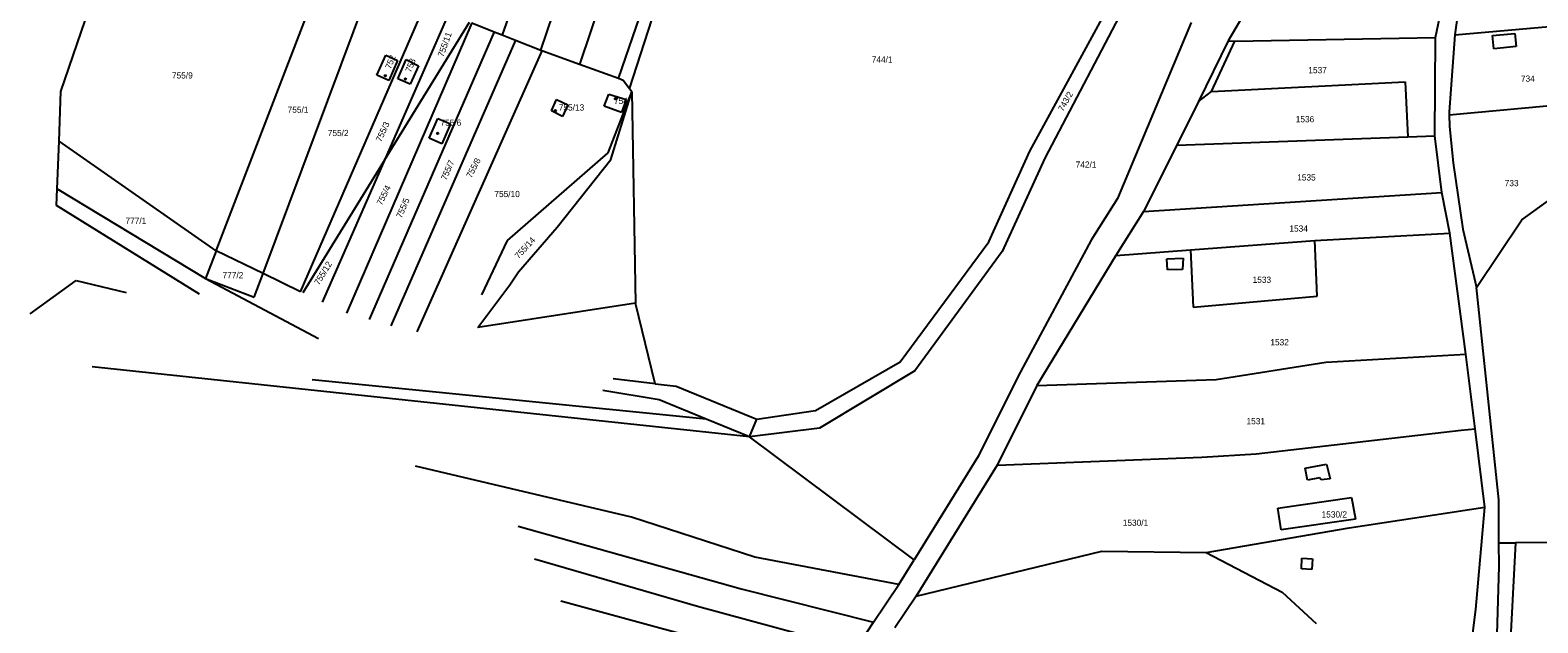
# Model space of a CAD drawing. Extents: x -563148 to -561712, y -1182311 to -1179502.
# Drawn here: x -562955.1 to -562591.4, y -1180918.5 to -1180775.6 of the extents above; entities that cross this region are included whole.
import ezdxf

# ---------------------------------------------------------------- set-up
doc = ezdxf.new("R2010")
doc.units = 0
for name, color, linetype in [('Vrstva 53', 7, 'Continuous'), ('Vrstva 55', 7, 'Continuous'), ('Vrstva 56', 7, 'Continuous'), ('Vrstva 57', 7, 'Continuous')]:
    doc.layers.add(name, color=color, linetype=linetype)

msp = doc.modelspace()

# ---------------------------------------------------------------- linework, layer by layer
at = {"layer": 'Vrstva 53'}
for p, q in [((-562595.23, -1180821.34), (-562581.87, -1180811.63)), ((-562606.16, -1180837.67), (-562595.23, -1180821.34)), ((-562600.82, -1180888.85), (-562606.16, -1180837.67)), ((-562600.76, -1180899.19), (-562600.82, -1180888.85)), ((-562600.76, -1180899.19), (-562596.76, -1180899.17)), ((-562585.46, -1180899.1), (-562596.76, -1180899.17))]:
    msp.add_line(p, q, dxfattribs=at)
at = {"layer": 'Vrstva 55'}
for p, q in [((-562827.69, -1180737.88), (-562841.24, -1180776.78)), ((-562831.89, -1180780.47), (-562818.35, -1180740.61)), ((-562713.92, -1180804.79), (-562679.66, -1180741.71)), ((-562676.72, -1180742.33), (-562710.29, -1180806.45)), ((-562808.91, -1180743.37), (-562822.56, -1180783.88)), ((-562813.19, -1180787.3), (-562799.04, -1180746.25)), ((-562947.69, -1180790.4), (-562936.28, -1180757.13)), ((-562810.53, -1180789.76), (-562798.99, -1180754.17)), ((-562616.02, -1180777.4), (-562611.28, -1180754.69)), ((-562910.23, -1180828.79), (-562883.84, -1180760.23)), ((-562898.92, -1180834.29), (-562872.15, -1180762.85)), ((-562656.73, -1180762.3), (-562666.05, -1180778.2)), ((-562609.42, -1180762.74), (-562611.42, -1180776.77)), ((-562854.17, -1180771.68), (-562869.66, -1180806.99)), ((-562889.9, -1180838.68), (-562861.36, -1180772.96)), ((-562848.59, -1180773.88), (-562878.81, -1180843.82)), ((-562869.66, -1180806.99), (-562849.15, -1180773.66)), ((-562848.59, -1180773.88), (-562843.19, -1180776.01)), ((-562675.01, -1180773.75), (-562692.75, -1180816.21)), ((-562611.42, -1180776.77), (-562580.34, -1180773.98)), ((-562843.19, -1180776.01), (-562873.34, -1180845.38)), ((-562838.01, -1180778.06), (-562868.07, -1180846.87)), ((-562843.19, -1180776.01), (-562841.24, -1180776.78)), ((-562841.24, -1180776.78), (-562838.01, -1180778.06)), ((-562838.01, -1180778.06), (-562831.89, -1180780.47)), ((-562666.05, -1180778.2), (-562673.21, -1180792.81)), ((-562666.05, -1180778.2), (-562664.45, -1180778.26)), ((-562664.45, -1180778.26), (-562616.02, -1180777.4)), ((-562616.22, -1180801.11), (-562616.02, -1180777.4)), ((-562611.42, -1180776.77), (-562612.79, -1180795.29)), ((-562871.47, -1180786.45), (-562869.33, -1180781.66)), ((-562869.33, -1180781.66), (-562866.46, -1180782.93)), ((-562866.46, -1180782.93), (-562868.59, -1180787.73)), ((-562866.44, -1180787.32), (-562864.41, -1180782.69)), ((-562864.41, -1180782.69), (-562861.41, -1180784.18)), ((-562831.63, -1180780.57), (-562861.81, -1180848.3)), ((-562831.89, -1180780.47), (-562831.63, -1180780.57)), ((-562822.56, -1180783.88), (-562831.63, -1180780.57)), ((-562868.59, -1180787.73), (-562871.47, -1180786.45)), ((-562861.41, -1180784.18), (-562863.39, -1180788.66)), ((-562813.19, -1180787.3), (-562822.56, -1180783.88)), ((-562948.15, -1180802.39), (-562947.69, -1180790.4)), ((-562863.39, -1180788.66), (-562866.44, -1180787.32)), ((-562812.04, -1180787.79), (-562813.19, -1180787.3)), ((-562810.53, -1180789.76), (-562812.04, -1180787.79)), ((-562809.98, -1180790.48), (-562810.53, -1180789.76)), ((-562673.21, -1180792.81), (-562670.1, -1180790.39)), ((-562670.1, -1180790.39), (-562623.35, -1180788.08)), ((-562623.35, -1180788.08), (-562622.72, -1180801.34)), ((-562829.33, -1180795.08), (-562828.14, -1180792.32)), ((-562828.14, -1180792.32), (-562825.38, -1180793.63)), ((-562825.38, -1180793.63), (-562826.69, -1180796.4)), ((-562816.65, -1180793.92), (-562815.47, -1180791.08)), ((-562812.45, -1180795.49), (-562816.65, -1180793.92)), ((-562815.63, -1180805.16), (-562809.98, -1180790.48)), ((-562815.47, -1180791.08), (-562811.28, -1180792.35)), ((-562814.99, -1180806.76), (-562809.98, -1180790.48)), ((-562811.28, -1180792.35), (-562812.45, -1180795.49)), ((-562673.21, -1180792.81), (-562678.47, -1180803.31)), ((-562612.76, -1180796.03), (-562577.23, -1180792.79)), ((-562858.86, -1180801.66), (-562856.77, -1180796.95)), ((-562856.77, -1180796.95), (-562853.69, -1180798.22)), ((-562826.69, -1180796.4), (-562829.33, -1180795.08)), ((-562612.79, -1180795.29), (-562612.76, -1180796.03)), ((-562612.76, -1180796.03), (-562612.65, -1180798.82)), ((-562853.69, -1180798.22), (-562855.77, -1180803)), ((-562678.47, -1180803.31), (-562622.72, -1180801.34)), ((-562622.72, -1180801.34), (-562616.22, -1180801.11)), ((-562614.54, -1180814.73), (-562616.22, -1180801.11)), ((-562612.65, -1180798.82), (-562611.78, -1180807.58)), ((-562948.58, -1180813.89), (-562948.15, -1180802.39)), ((-562910.23, -1180828.79), (-562948.15, -1180802.39)), ((-562855.77, -1180803), (-562858.86, -1180801.66)), ((-562723.82, -1180826.62), (-562713.92, -1180804.79)), ((-562678.47, -1180803.31), (-562686.49, -1180819.35)), ((-562869.66, -1180806.99), (-562889.33, -1180838.95)), ((-562869.66, -1180806.99), (-562884.68, -1180841.22)), ((-562839.98, -1180826.34), (-562815.63, -1180805.16)), ((-562827.99, -1180823.07), (-562814.99, -1180806.76)), ((-562710.29, -1180806.45), (-562720.59, -1180828.99)), ((-562611.78, -1180807.58), (-562609.44, -1180823.56)), ((-562948.73, -1180817.87), (-562948.58, -1180813.89)), ((-562948.58, -1180813.89), (-562912.81, -1180835.51)), ((-562686.49, -1180819.35), (-562614.54, -1180814.73)), ((-562612.58, -1180824.59), (-562614.54, -1180814.73)), ((-562914.25, -1180839.24), (-562948.73, -1180817.87)), ((-562692.75, -1180816.21), (-562699.12, -1180826.28)), ((-562686.49, -1180819.35), (-562693.15, -1180829.92)), ((-562837.3, -1180833.89), (-562827.99, -1180823.07)), ((-562846.17, -1180839.44), (-562839.98, -1180826.34)), ((-562745.24, -1180855.55), (-562723.82, -1180826.62)), ((-562699.12, -1180826.28), (-562716.73, -1180859.03)), ((-562675.18, -1180828.56), (-562645.15, -1180826.33)), ((-562645.15, -1180826.33), (-562612.58, -1180824.59)), ((-562644.58, -1180839.73), (-562645.15, -1180826.33)), ((-562608.71, -1180853.76), (-562612.58, -1180824.59)), ((-562609.44, -1180823.56), (-562606.16, -1180837.67)), ((-562910.23, -1180828.79), (-562912.81, -1180835.51)), ((-562898.92, -1180834.29), (-562910.23, -1180828.79)), ((-562720.59, -1180828.99), (-562741.68, -1180857.76)), ((-562693.15, -1180829.92), (-562712.25, -1180861.26)), ((-562693.15, -1180829.92), (-562675.18, -1180828.56)), ((-562675.18, -1180828.56), (-562674.54, -1180842.37)), ((-562839.35, -1180837.04), (-562837.3, -1180833.89)), ((-562955.11, -1180844.03), (-562944.03, -1180835.96)), ((-562944.03, -1180835.96), (-562931.96, -1180838.82)), ((-562912.81, -1180835.51), (-562885.56, -1180849.96)), ((-562912.81, -1180835.51), (-562901.05, -1180839.97)), ((-562901.05, -1180839.97), (-562898.92, -1180834.29)), ((-562889.9, -1180838.68), (-562898.92, -1180834.29)), ((-562847.12, -1180847.3), (-562839.35, -1180837.04)), ((-562674.54, -1180842.37), (-562644.58, -1180839.73)), ((-562809.1, -1180841.43), (-562847.12, -1180847.3)), ((-562804.32, -1180860.84), (-562809.1, -1180841.43)), ((-562765.6, -1180867.27), (-562745.24, -1180855.55)), ((-562668.98, -1180859.83), (-562642.48, -1180855.62)), ((-562642.48, -1180855.62), (-562608.71, -1180853.76)), ((-562606.5, -1180871.69), (-562608.71, -1180853.76)), ((-562781.53, -1180873.68), (-562940.16, -1180856.77)), ((-562741.68, -1180857.76), (-562764.68, -1180871.53)), ((-562716.73, -1180859.03), (-562726.31, -1180878.23)), ((-562792.01, -1180869.38), (-562887.1, -1180859.94)), ((-562803.36, -1180864.72), (-562816.94, -1180862.45)), ((-562804.32, -1180860.84), (-562814.42, -1180859.7)), ((-562804.32, -1180860.84), (-562799.29, -1180861.41)), ((-562799.29, -1180861.41), (-562780.96, -1180868.89)), ((-562712.25, -1180861.26), (-562721.82, -1180880.47)), ((-562712.25, -1180861.26), (-562668.98, -1180859.83)), ((-562792.01, -1180869.38), (-562803.36, -1180864.72)), ((-562781.53, -1180873.68), (-562792.01, -1180869.38)), ((-562781.53, -1180873.68), (-562779.77, -1180869.37)), ((-562780.96, -1180868.89), (-562779.77, -1180869.37)), ((-562779.77, -1180869.37), (-562765.6, -1180867.27)), ((-562764.68, -1180871.53), (-562781.53, -1180873.68)), ((-562741.86, -1180903.31), (-562781.53, -1180873.68)), ((-562659.3, -1180877.73), (-562609.87, -1180872.08)), ((-562609.87, -1180872.08), (-562606.5, -1180871.69)), ((-562604.17, -1180890.63), (-562606.5, -1180871.69)), ((-562672.43, -1180878.57), (-562659.3, -1180877.73)), ((-562810.02, -1180893.01), (-562862.12, -1180880.76)), ((-562726.31, -1180878.23), (-562741.86, -1180903.31)), ((-562721.82, -1180880.47), (-562741.39, -1180912.04)), ((-562721.82, -1180880.47), (-562672.43, -1180878.57)), ((-562654.07, -1180890.84), (-562636.35, -1180888.29)), ((-562636.35, -1180888.29), (-562635.4, -1180893.51)), ((-562653.31, -1180896.09), (-562654.07, -1180890.84)), ((-562636.85, -1180895.58), (-562604.17, -1180890.63)), ((-562606.3, -1180915.26), (-562604.17, -1180890.63)), ((-562837.38, -1180895.21), (-562783.58, -1180910.33)), ((-562780.31, -1180902.65), (-562810.02, -1180893.01)), ((-562671.35, -1180901.55), (-562636.85, -1180895.58)), ((-562635.4, -1180893.51), (-562653.31, -1180896.09)), ((-562600.73, -1180904.79), (-562600.76, -1180899.19)), ((-562596.76, -1180899.17), (-562600, -1180960.38)), ((-562833.47, -1180903.03), (-562794.13, -1180914.5)), ((-562745.55, -1180909.26), (-562780.31, -1180902.65)), ((-562741.39, -1180912.04), (-562696.56, -1180901.24)), ((-562696.56, -1180901.24), (-562671.35, -1180901.55)), ((-562671.35, -1180901.55), (-562653.04, -1180911.12)), ((-562745.55, -1180909.26), (-562741.86, -1180903.31)), ((-562601.86, -1180943.74), (-562600.73, -1180904.79)), ((-562783.58, -1180910.33), (-562751.61, -1180918.35)), ((-562751.61, -1180918.35), (-562745.55, -1180909.26)), ((-562827.09, -1180913.2), (-562760.24, -1180931.32)), ((-562741.39, -1180912.04), (-562746.48, -1180919.67)), ((-562653.04, -1180911.12), (-562644.85, -1180918.62)), ((-562794.13, -1180914.5), (-562755.91, -1180924.81)), ((-562611.14, -1180952.82), (-562606.3, -1180915.26)), ((-562755.91, -1180924.81), (-562751.61, -1180918.35))]:
    msp.add_line(p, q, dxfattribs=at)
at = {"layer": 'Vrstva 56'}
for p, q in [((-562670.1, -1180790.39), (-562664.45, -1180778.26)), ((-562602.27, -1180776.94), (-562596.93, -1180776.42)), ((-562601.98, -1180780.11), (-562602.27, -1180776.94)), ((-562596.6, -1180779.53), (-562601.98, -1180780.11)), ((-562596.93, -1180776.42), (-562596.6, -1180779.53)), ((-562809.98, -1180790.48), (-562809.1, -1180841.43)), ((-562680.84, -1180830.75), (-562676.97, -1180830.62)), ((-562680.72, -1180833.36), (-562680.84, -1180830.75)), ((-562677.07, -1180833.28), (-562680.72, -1180833.36)), ((-562676.97, -1180830.62), (-562677.07, -1180833.28)), ((-562647.51, -1180881.17), (-562642.32, -1180880.2)), ((-562646.97, -1180884.08), (-562647.51, -1180881.17)), ((-562642.32, -1180880.2), (-562641.51, -1180883.76)), ((-562644.01, -1180883.53), (-562646.97, -1180884.08)), ((-562643.67, -1180883.99), (-562644.01, -1180883.53)), ((-562641.51, -1180883.76), (-562643.67, -1180883.99)), ((-562648.39, -1180905.5), (-562648.32, -1180902.93)), ((-562648.32, -1180902.93), (-562645.76, -1180903.09)), ((-562645.76, -1180903.09), (-562645.86, -1180905.61)), ((-562645.86, -1180905.61), (-562648.39, -1180905.5))]:
    msp.add_line(p, q, dxfattribs=at)
at = {"layer": 'Vrstva 57'}
for centre in [(-562869.43, -1180786.62), (-562864.57, -1180787.4), (-562813.89, -1180792.14), (-562828.42, -1180795), (-562856.79, -1180800.48)]:
    msp.add_circle(centre, 0.175, dxfattribs=at)

# ---------------------------------------------------------------- texts
for s, rotation, p in [('755/11', 70.4016, (-562855.41, -1180782.21)), ('752', 68.5571, (-562868.11, -1180785.12)), ('753', 68.3797, (-562863.27, -1180785.92)), ('743/2', 60.2063, (-562705.92, -1180795.33)), ('755/3', 65.6259, (-562870.41, -1180802.69)), ('755/7', 66.3617, (-562854.71, -1180811.95)), ('755/8', 62.2161, (-562848.68, -1180811.39)), ('755/4', 63.507, (-562870.27, -1180817.98)), ('755/5', 66.523, (-562865.5, -1180821.07)), ('755/14', 47.3924, (-562837.26, -1180830.86)), ('755/12', 58.5367, (-562885.42, -1180837.2))]:
    msp.add_text(s, height=1.5, rotation=rotation, dxfattribs=at).set_placement(p)
for s, p in [('744/1', (-562752.07, -1180783.45)), ('755/9', (-562920.9, -1180787.27)), ('1537', (-562646.74, -1180786)), ('734', (-562595.45, -1180788.05)), ('755/1', (-562892.99, -1180795.54)), ('755/13', (-562827.57, -1180795)), ('754', (-562814.26, -1180793.42)), ('755/6', (-562856.11, -1180798.66)), ('1536', (-562649.78, -1180797.82)), ('755/2', (-562883.31, -1180801.16)), ('742/1', (-562702.87, -1180808.78)), ('1535', (-562649.42, -1180811.86)), ('733', (-562599.36, -1180813.23)), ('755/10', (-562843.11, -1180815.86)), ('777/1', (-562932.12, -1180822.33)), ('1534', (-562651.31, -1180824.2)), ('777/2', (-562908.7, -1180835.44)), ('1533', (-562660.18, -1180836.53)), ('1532', (-562655.9, -1180851.6)), ('1531', (-562661.65, -1180870.62)), ('1530/2', (-562643.54, -1180893.1)), ('1530/1', (-562691.51, -1180895.1))]:
    msp.add_text(s, height=1.5, dxfattribs=at).set_placement(p)

doc.saveas('drawing.dxf')
